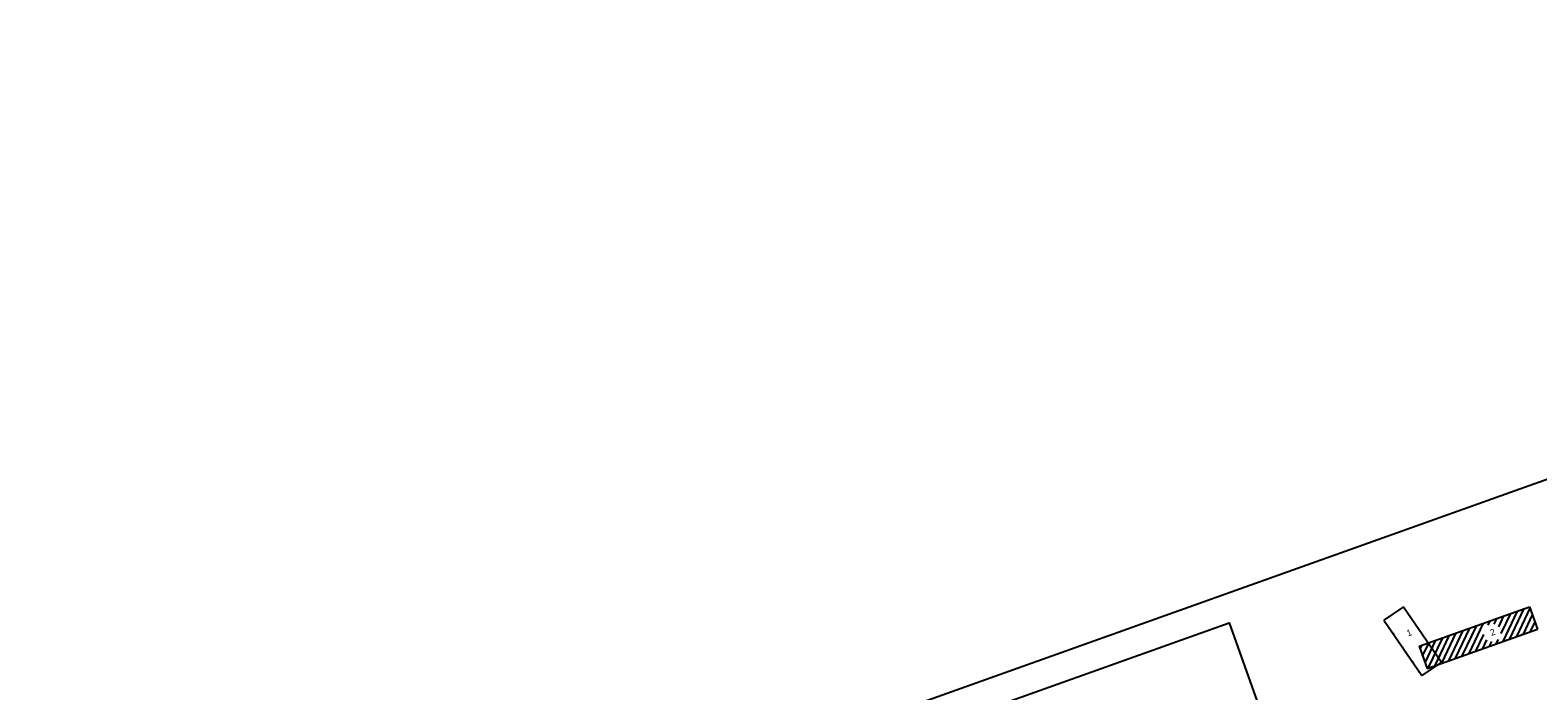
# Model space of a CAD drawing. Extents: x -734423 to 647242, y -1165906 to -111601.
# Drawn here: x -532951.8 to -532656.7, y -1114292.8 to -1114163.4 of the extents above; entities that cross this region are included whole.
import ezdxf

# ---------------------------------------------------------------- set-up
doc = ezdxf.new("R2010")
doc.units = 0
for name, color, linetype in [('Vrstva 2', 7, 'Continuous'), ('Vrstva 3', 7, 'Continuous'), ('Vrstva 4', 7, 'Continuous')]:
    doc.layers.add(name, color=color, linetype=linetype)

msp = doc.modelspace()

# ---------------------------------------------------------------- linework, layer by layer
at = {"layer": 'Vrstva 2'}
for p, q in [((-532663.88, -1114281.52), (-532662.03, -1114277.62)), ((-532663.51, -1114283.08), (-532660.7, -1114277.15)), ((-532662.18, -1114282.6), (-532659.37, -1114276.67)), ((-532660.85, -1114282.13), (-532658.22, -1114276.59)), ((-532659.52, -1114281.65), (-532657.75, -1114277.92)), ((-532674.17, -1114286.88), (-532671.36, -1114280.95)), ((-532672.84, -1114286.4), (-532670.03, -1114280.47)), ((-532671.51, -1114285.93), (-532668.69, -1114280)), ((-532670.17, -1114285.45), (-532667.36, -1114279.52)), ((-532666.45, -1114279.92), (-532666.03, -1114279.05)), ((-532665.25, -1114279.74), (-532664.7, -1114278.57)), ((-532664.37, -1114280.22), (-532663.37, -1114278.1)), ((-532658.19, -1114281.18), (-532657.27, -1114279.26)), ((-532656.85, -1114280.7), (-532656.8, -1114280.59)), ((-532679.74, -1114284.63), (-532679.35, -1114283.8)), ((-532679.27, -1114285.96), (-532678.02, -1114283.32)), ((-532678.79, -1114287.29), (-532676.69, -1114282.85)), ((-532678.17, -1114288.3), (-532675.35, -1114282.37)), ((-532676.84, -1114287.83), (-532674.02, -1114281.9)), ((-532675.5, -1114287.35), (-532672.69, -1114281.42)), ((-532668.84, -1114284.98), (-532667.3, -1114281.72)), ((-532667.51, -1114284.5), (-532666.69, -1114282.76)), ((-532666.18, -1114284.03), (-532665.76, -1114283.14)), ((-532664.85, -1114283.55), (-532664.44, -1114282.7))]:
    msp.add_line(p, q, dxfattribs=at)
at = {"layer": 'Vrstva 3'}
msp.add_lwpolyline([(-532787.74, -1114304.65), (-532717.13, -1114279.48), (-532706.54, -1114309.16), (-532777.16, -1114334.34)], close=True, dxfattribs=at)
at = {"layer": 'Vrstva 4'}
for p, q in [((-533100.62, -1114410.25), (-532408.31, -1114163.4)), ((-532683.01, -1114276.31), (-532686.84, -1114278.94)), ((-532683.01, -1114276.31), (-532675.6, -1114287.14)), ((-532679.96, -1114284.02), (-532658.33, -1114276.3)), ((-532658.33, -1114276.3), (-532656.77, -1114280.67)), ((-532686.84, -1114278.94), (-532679.43, -1114289.76)), ((-532678.4, -1114288.39), (-532656.77, -1114280.67)), ((-532684.87, -1114281.56), (-532684.99, -1114281.64)), ((-532666.09, -1114283.84), (-532666.04, -1114283.98)), ((-532663, -1114282.74), (-532662.95, -1114282.88)), ((-532659.91, -1114281.64), (-532659.86, -1114281.78)), ((-532683.02, -1114284.27), (-532683.14, -1114284.35)), ((-532679.96, -1114284.02), (-532678.4, -1114288.39)), ((-532672.27, -1114286.05), (-532672.22, -1114286.18)), ((-532669.18, -1114284.95), (-532669.13, -1114285.08)), ((-532681.16, -1114286.98), (-532681.28, -1114287.06)), ((-532675.6, -1114287.14), (-532679.43, -1114289.76)), ((-532675.36, -1114287.15), (-532675.31, -1114287.29))]:
    msp.add_line(p, q, dxfattribs=at)

# ---------------------------------------------------------------- texts
at = {"layer": 'Vrstva 3'}
for s, p in [('1', (-532682.14, -1114282.14)), ('2', (-532665.79, -1114282.02))]:
    msp.add_text(s, height=1.25, rotation=19.5946, dxfattribs=at).set_placement(p)

doc.saveas('drawing.dxf')
